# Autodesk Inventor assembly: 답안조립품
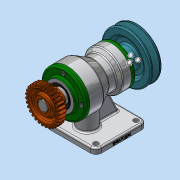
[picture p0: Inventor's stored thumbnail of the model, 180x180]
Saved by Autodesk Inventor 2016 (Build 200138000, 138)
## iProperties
Created: 2019-01
Part Number: 답안조립품
Document SubType Name: Assembly
Designer: MIRAE
Author: MIRAE
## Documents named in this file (15)
- C:\Users\MIRAE\Desktop\490107V1035\답안조립품.iam
- C:\Users\MIRAE\Desktop\490107V1035\본체.ipt
- C:\Users\MIRAE\Desktop\490107V1035\축.ipt
- C:\Users\MIRAE\Desktop\490107V1035\키 6 x 6 x 18.ipt
- C:\Users\MIRAE\Desktop\490107V1035\키 5 x 5 x 20.ipt
- C:\Users\MIRAE\Desktop\490107V1035\앞커버.ipt
- C:\Users\MIRAE\Desktop\490107V1035\베어링 6205.ipt
- C:\Users\MIRAE\Desktop\490107V1035\베어링 6203.ipt
- C:\Users\MIRAE\Desktop\490107V1035\뒤커버.ipt
- C:\Users\MIRAE\Desktop\490107V1035\오일 실 25 38 8.ipt
- C:\Users\MIRAE\Desktop\490107V1035\오일 실 17 30 8.ipt
- C:\Users\MIRAE\Desktop\490107V1035\볼트 M4.ipt
- C:\Users\MIRAE\Desktop\490107V1035\V-벨트풀리.ipt
- C:\Users\MIRAE\Desktop\490107V1035\멈춤나사 M3.ipt
- C:\Users\MIRAE\Desktop\490107V1035\스퍼기어.ipt
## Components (1 placed, 1 different names)
1. V-벨트풀리:1
